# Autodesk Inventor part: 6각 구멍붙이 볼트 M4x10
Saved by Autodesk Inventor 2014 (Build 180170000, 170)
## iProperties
Created: 2026-03
Part Number: 6각 구멍붙이 볼트 M4x10
Material: 강철, 연강
Document SubType Name: Modeling
Designer: dg
Density: 7.86 g/cm^3
Appearance: 강철
Mass: 2.0371 g
Surface Area: 3.0572 cm^2
Volume: 0.259174 cm^3
Author: jhkim
Description: 6각머리 태핑 나사
Creation Date: 2025-06-27
Sending System: Autodesk Inventor 2026
Preprocessor: ST-DEVELOPER v20.1
Author: dg
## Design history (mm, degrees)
node "6각 구멍붙이 볼트 M4x101"
body "Solid1"
node "기준1"
